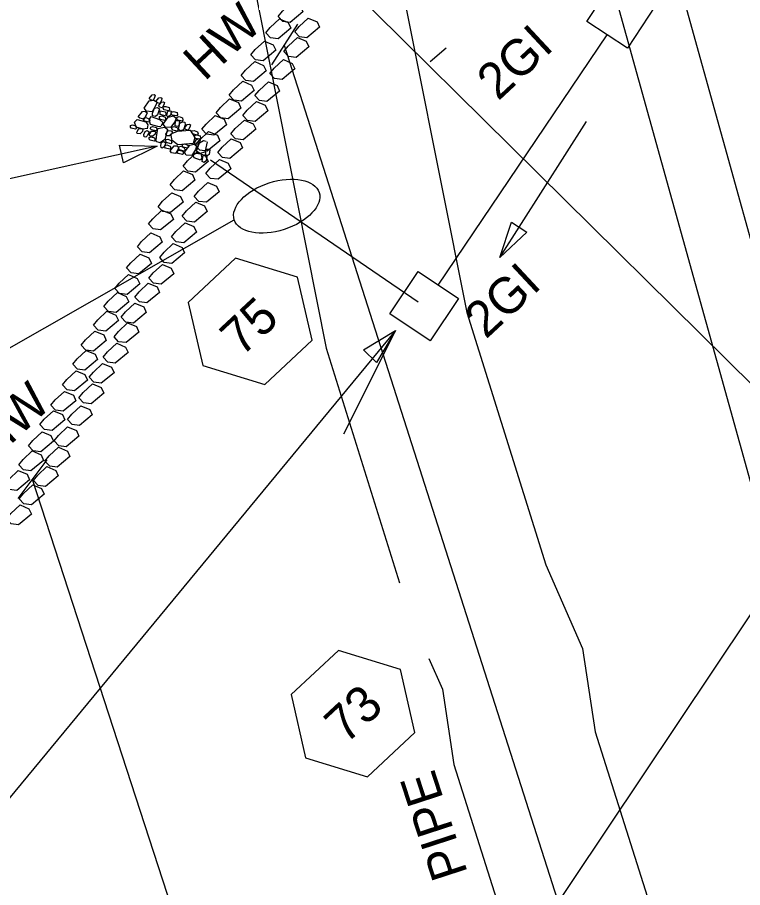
# Model space of a CAD drawing. Extents: x 2384780 to 2405432, y 547869 to 573706.
# Drawn here: x 2399532.6 to 2399632.8, y 561289.2 to 561409.4 of the extents above; entities that cross this region are included whole.
import ezdxf

# ---------------------------------------------------------------- set-up
doc = ezdxf.new("R2010")
doc.units = 0
for name, color, linetype in [('Old_Level_1', 7, 'Continuous'), ('Old_Level_10', 7, 'Continuous'), ('Old_Level_19', 7, 'Continuous'), ('Old_Level_20', 7, 'Continuous'), ('Old_Level_5', 7, 'Continuous'), ('Old_Level_63', 7, 'Continuous'), ('Old_Level_9', 7, 'Continuous'), ('Prop Buffer Zone 1', 7, 'Continuous'), ('Prop Buffer Zone 2', 7, 'Continuous'), ('Prop Drainage Box Number Symbol CELL', 7, 'Continuous')]:
    doc.layers.add(name, color=color, linetype=linetype)

# ---------------------------------------------------------------- blocks, each defined once
blk = doc.blocks.new('BUBBLE')
at = {"layer": 'Old_Level_10'}
blk.add_ellipse((0, 0), major_axis=(192.5, 153.8), ratio=0.548538, dxfattribs=at)

msp = doc.modelspace()

# ---------------------------------------------------------------- linework, layer by layer
at = {"layer": 'Old_Level_1'}
for p, q in [((2399590.77, 561372.41), (2399614.13, 561406.99)), ((2399641.65, 561180.06), (2399569.52, 561405.53)), ((2399551.91, 561391.59), (2399515.09, 561383.45)), ((2399588.02, 561370.04), (2399559.31, 561389.68)), ((2399605.31, 561128.58), (2399534.7, 561345.56))]:
    msp.add_line(p, q, dxfattribs=at)
for points in [[(2399551.93, 561397.67), (2399551.72, 561397.19), (2399551.23, 561396.35), (2399550.45, 561396.43), (2399550.15, 561396.87), (2399550.85, 561397.85), (2399551.48, 561397.95), (2399551.93, 561397.67)], [(2399551.67, 561398.63), (2399551.58, 561398.33), (2399551.36, 561397.89), (2399551.01, 561397.98), (2399550.83, 561398.18), (2399551.23, 561398.68), (2399551.53, 561398.75), (2399551.67, 561398.63)], [(2399552.6, 561398.22), (2399552.51, 561397.92), (2399552.28, 561397.48), (2399551.94, 561397.57), (2399551.75, 561397.77), (2399552.15, 561398.27), (2399552.45, 561398.34), (2399552.6, 561398.22)], [(2399552.94, 561397.62), (2399552.86, 561397.32), (2399552.64, 561396.88), (2399552.29, 561396.97), (2399552.11, 561397.17), (2399552.51, 561397.67), (2399552.81, 561397.74), (2399552.94, 561397.62)], [(2399550.55, 561396.22), (2399550.42, 561395.88), (2399550.08, 561395.34), (2399549.53, 561395.45), (2399549.33, 561395.66), (2399549.91, 561396.4), (2399550.29, 561396.44), (2399550.55, 561396.22)], [(2399551.28, 561395.78), (2399551.31, 561396.17), (2399551.58, 561396.84), (2399551.99, 561396.93), (2399552.25, 561396.76), (2399552, 561395.95), (2399551.71, 561395.69), (2399551.28, 561395.78)], [(2399552.37, 561396.47), (2399552.57, 561396.43), (2399553.09, 561396.35), (2399553.13, 561395.96), (2399553.03, 561395.81), (2399552.36, 561395.96), (2399552.34, 561396.22), (2399552.37, 561396.47)], [(2399552.78, 561397.06), (2399553.11, 561397.08), (2399553.6, 561396.94), (2399553.63, 561396.65), (2399553.54, 561396.5), (2399552.9, 561396.62), (2399552.77, 561396.84), (2399552.78, 561397.06)], [(2399553.2, 561395.73), (2399553.25, 561395.95), (2399553.42, 561396.42), (2399553.72, 561396.49), (2399553.86, 561396.42), (2399553.79, 561395.88), (2399553.53, 561395.69), (2399553.31, 561395.7)], [(2399553.93, 561396.31), (2399554.2, 561396.4), (2399554.68, 561396.24), (2399554.74, 561395.93), (2399554.64, 561395.77), (2399554.02, 561395.89), (2399553.89, 561396.11), (2399553.93, 561396.31)], [(2399550.51, 561394.02), (2399550, 561393.97), (2399549.01, 561394.23), (2399548.81, 561394.92), (2399549.19, 561395.3), (2399550.37, 561394.94), (2399550.65, 561394.54), (2399550.57, 561393.98)], [(2399550.09, 561395.47), (2399550.37, 561395.55), (2399550.85, 561395.4), (2399550.92, 561395.09), (2399550.82, 561394.93), (2399550.19, 561395.06), (2399550.05, 561395.27), (2399550.09, 561395.47)], [(2399552.45, 561394.26), (2399552.01, 561394.32), (2399550.99, 561394.6), (2399550.84, 561395.26), (2399551.11, 561395.71), (2399552.27, 561395.3), (2399552.7, 561394.85), (2399552.48, 561394.37)], [(2399552.26, 561395.71), (2399552.57, 561395.79), (2399553.04, 561395.62), (2399553.11, 561395.31), (2399552.98, 561395.17), (2399552.4, 561395.3), (2399552.25, 561395.49), (2399552.26, 561395.71)], [(2399554.58, 561395.47), (2399554.39, 561394.97), (2399553.77, 561394.16), (2399553.1, 561394.22), (2399552.75, 561394.65), (2399553.47, 561395.61), (2399554.17, 561395.8), (2399554.58, 561395.47)], [(2399554.41, 561394.4), (2399554.43, 561394.64), (2399554.52, 561395.17), (2399554.9, 561395.16), (2399555.04, 561395.07), (2399554.91, 561394.43), (2399554.72, 561394.33), (2399554.41, 561394.4)], [(2399554.69, 561395.59), (2399554.96, 561395.68), (2399555.44, 561395.52), (2399555.5, 561395.21), (2399555.4, 561395.05), (2399554.78, 561395.18), (2399554.65, 561395.39), (2399554.69, 561395.59)], [(2399548.23, 561394.47), (2399548.51, 561394.57), (2399548.98, 561394.4), (2399549.06, 561394.09), (2399548.93, 561393.95), (2399548.35, 561394.08), (2399548.24, 561394.24), (2399548.23, 561394.47)], [(2399549.96, 561393.93), (2399549.89, 561393.62), (2399549.58, 561393.32), (2399549.19, 561393.35), (2399549.1, 561393.55), (2399549.41, 561394.06), (2399549.8, 561394.03), (2399549.96, 561393.93)], [(2399551.05, 561394.24), (2399551.29, 561394.31), (2399551.84, 561394.16), (2399551.9, 561393.85), (2399551.77, 561393.72), (2399551.15, 561393.84), (2399551.03, 561393.99), (2399551.05, 561394.24)], [(2399551.8, 561392.34), (2399551.82, 561392.88), (2399552.02, 561394.05), (2399552.96, 561394.21), (2399553.37, 561393.96), (2399552.98, 561392.53), (2399552.36, 561392.08), (2399551.74, 561392.23)], [(2399554, 561394.23), (2399554.26, 561394.33), (2399554.73, 561394.13), (2399554.82, 561393.87), (2399554.7, 561393.68), (2399554.09, 561393.82), (2399553.96, 561394.04), (2399554, 561394.23)], [(2399555.75, 561394.9), (2399555.78, 561394.54), (2399555.59, 561393.86), (2399555.15, 561393.74), (2399554.9, 561393.9), (2399555.07, 561394.76), (2399555.44, 561394.98), (2399555.75, 561394.9)], [(2399556.54, 561394.54), (2399556.45, 561394.24), (2399556.23, 561393.8), (2399555.88, 561393.89), (2399555.69, 561394.09), (2399556.09, 561394.59), (2399556.4, 561394.66), (2399556.54, 561394.54)], [(2399550.14, 561392.87), (2399550.1, 561393.21), (2399550.26, 561393.62), (2399550.56, 561393.76), (2399550.82, 561393.6), (2399550.56, 561393.05), (2399550.35, 561392.84), (2399550.14, 561392.87)], [(2399550.83, 561392.79), (2399551.1, 561392.9), (2399551.57, 561392.73), (2399551.66, 561392.43), (2399551.53, 561392.29), (2399550.95, 561392.41), (2399550.83, 561392.57), (2399550.83, 561392.79)], [(2399551.7, 561393.57), (2399551.64, 561393.25), (2399551.34, 561392.96), (2399550.94, 561392.97), (2399550.85, 561393.17), (2399551.16, 561393.68), (2399551.55, 561393.67), (2399551.7, 561393.57)], [(2399554, 561393.64), (2399553.94, 561393.32), (2399553.63, 561393.03), (2399553.24, 561393.04), (2399553.15, 561393.24), (2399553.46, 561393.75), (2399553.84, 561393.74), (2399554, 561393.64)], [(2399553.97, 561393.33), (2399554.75, 561393.67), (2399556.49, 561393.79), (2399557.14, 561392.78), (2399556.92, 561391.98), (2399554.77, 561391.77), (2399554.01, 561392.38), (2399553.8, 561393.31)], [(2399556.74, 561393.7), (2399557.04, 561393.75), (2399557.52, 561393.59), (2399557.6, 561393.31), (2399557.48, 561393.12), (2399556.85, 561393.29), (2399556.73, 561393.48), (2399556.74, 561393.7)], [(2399557.12, 561393.09), (2399557.39, 561393.18), (2399557.86, 561393.02), (2399557.93, 561392.71), (2399557.83, 561392.55), (2399557.21, 561392.68), (2399557.08, 561392.89), (2399557.12, 561393.09)], [(2399552.47, 561391.43), (2399552.42, 561391.69), (2399552.54, 561392.1), (2399552.86, 561392.25), (2399553.14, 561392.08), (2399552.88, 561391.53), (2399552.64, 561391.33), (2399552.47, 561391.43)], [(2399552.98, 561391.71), (2399553.26, 561391.79), (2399553.73, 561391.62), (2399553.81, 561391.33), (2399553.68, 561391.19), (2399553.1, 561391.31), (2399552.99, 561391.48), (2399552.98, 561391.71)], [(2399553.15, 561392.51), (2399553.41, 561392.57), (2399553.86, 561392.39), (2399553.96, 561392.1), (2399553.83, 561391.91), (2399553.24, 561392.09), (2399553.14, 561392.29), (2399553.15, 561392.51)], [(2399554.9, 561391.51), (2399554.78, 561391.1), (2399554.47, 561390.59), (2399553.91, 561390.67), (2399553.73, 561390.97), (2399554.26, 561391.65), (2399554.65, 561391.66), (2399554.9, 561391.51)], [(2399554.93, 561391.51), (2399555.24, 561391.58), (2399555.68, 561391.38), (2399555.78, 561391.11), (2399555.66, 561390.92), (2399555.02, 561391.1), (2399554.92, 561391.29), (2399554.93, 561391.51)], [(2399555.43, 561391.83), (2399555.7, 561391.92), (2399556.17, 561391.75), (2399556.26, 561391.45), (2399556.13, 561391.31), (2399555.54, 561391.44), (2399555.42, 561391.61), (2399555.43, 561391.83)], [(2399557.41, 561391.64), (2399557.25, 561391.16), (2399556.72, 561390.3), (2399555.96, 561390.37), (2399555.72, 561390.75), (2399556.43, 561391.76), (2399557, 561391.88), (2399557.41, 561391.64)], [(2399557.88, 561392.41), (2399557.77, 561392.21), (2399557.54, 561391.83), (2399557.22, 561391.89), (2399557.06, 561391.99), (2399557.38, 561392.5), (2399557.72, 561392.64), (2399557.88, 561392.41)], [(2399558.83, 561392.21), (2399558.77, 561391.77), (2399558.51, 561390.78), (2399557.82, 561390.59), (2399557.39, 561390.91), (2399557.77, 561392.08), (2399558.33, 561392.4), (2399558.72, 561392.28)], [(2399554.73, 561390.96), (2399555.01, 561391.06), (2399555.48, 561390.89), (2399555.56, 561390.58), (2399555.43, 561390.44), (2399554.85, 561390.58), (2399554.72, 561390.74), (2399554.73, 561390.96)], [(2399556.98, 561390.64), (2399557.33, 561390.64), (2399557.95, 561390.52), (2399558.12, 561390), (2399557.92, 561389.66), (2399557.05, 561389.97), (2399556.9, 561390.29), (2399556.98, 561390.64)], [(2399558.58, 561390.43), (2399558.64, 561390.65), (2399558.7, 561391.19), (2399559.05, 561391.2), (2399559.21, 561391.1), (2399559.12, 561390.44), (2399558.83, 561390.27), (2399558.58, 561390.43)], [(2399558.16, 561389.5), (2399558.21, 561389.74), (2399558.29, 561390.31), (2399558.63, 561390.27), (2399558.79, 561390.18), (2399558.69, 561389.57), (2399558.41, 561389.35), (2399558.16, 561389.5)]]:
    msp.add_lwpolyline(points, dxfattribs=at)
for points in [[(2399546.75, 561391.73), (2399551.91, 561391.59), (2399547.29, 561389.29)], [(2399584.09, 561368.41), (2399587.98, 561374.26), (2399593.57, 561370.55), (2399589.68, 561364.71)]]:
    msp.add_lwpolyline(points, close=True, dxfattribs=at)
at = {"layer": 'Old_Level_10'}
for p, q in [((2399672.4, 561240.4), (2399616.91, 561439.98)), ((2399665.8, 561230.54), (2399610.31, 561430.11))]:
    msp.add_line(p, q, dxfattribs=at)
at = {"layer": 'Old_Level_19'}
msp.add_lwpolyline([(2399935.16, 561841.93), (2399903.83, 561780.72), (2399876, 561728.1), (2399849.43, 561679.29), (2399802.46, 561596.2), (2399773.68, 561547.14), (2399723.96, 561465.41), (2399672.86, 561385.1), (2399604.3, 561282.61), (2399518.27, 561161.65)], dxfattribs=at)
at = {"layer": 'Old_Level_20'}
for points in [[(2399568.64, 561409.53), (2399569.24, 561410.27), (2399570.51, 561411.45), (2399571.73, 561410.94), (2399572.08, 561410.17), (2399570.33, 561408.71), (2399569.28, 561408.84), (2399568.64, 561409.53)], [(2399566.96, 561407.27), (2399567.56, 561408), (2399568.83, 561409.19), (2399570.05, 561408.67), (2399570.4, 561407.9), (2399568.65, 561406.44), (2399567.6, 561406.58), (2399566.96, 561407.27)], [(2399570.94, 561407.39), (2399571.54, 561408.13), (2399572.81, 561409.31), (2399574.03, 561408.8), (2399574.38, 561408.03), (2399572.62, 561406.57), (2399571.58, 561406.7), (2399570.94, 561407.39)], [(2399564.88, 561404.21), (2399565.48, 561404.95), (2399566.75, 561406.13), (2399567.97, 561405.62), (2399568.32, 561404.85), (2399566.56, 561403.39), (2399565.52, 561403.52), (2399564.88, 561404.21)], [(2399569.44, 561404.68), (2399570.04, 561405.42), (2399571.31, 561406.61), (2399572.53, 561406.09), (2399572.88, 561405.32), (2399571.13, 561403.86), (2399570.08, 561403.99), (2399569.44, 561404.68)], [(2399563.54, 561401.36), (2399564.14, 561402.09), (2399565.42, 561403.28), (2399566.64, 561402.76), (2399566.98, 561402), (2399565.23, 561400.54), (2399564.19, 561400.67), (2399563.54, 561401.36)], [(2399567.51, 561401.64), (2399568.11, 561402.37), (2399569.38, 561403.56), (2399570.6, 561403.04), (2399570.95, 561402.27), (2399569.19, 561400.81), (2399568.15, 561400.95), (2399567.51, 561401.64)], [(2399561.9, 561398.64), (2399562.49, 561399.37), (2399563.77, 561400.56), (2399564.99, 561400.04), (2399565.34, 561399.27), (2399563.58, 561397.82), (2399562.54, 561397.95), (2399561.9, 561398.64)], [(2399565.42, 561398.58), (2399566.02, 561399.31), (2399567.3, 561400.5), (2399568.52, 561399.98), (2399568.86, 561399.22), (2399567.11, 561397.76), (2399566.07, 561397.89), (2399565.42, 561398.58)], [(2399560.07, 561396.21), (2399560.67, 561396.95), (2399561.94, 561398.13), (2399563.16, 561397.62), (2399563.51, 561396.85), (2399561.76, 561395.39), (2399560.71, 561395.52), (2399560.07, 561396.21)], [(2399563.78, 561395.86), (2399564.37, 561396.59), (2399565.65, 561397.78), (2399566.87, 561397.26), (2399567.22, 561396.49), (2399565.46, 561395.03), (2399564.42, 561395.17), (2399563.78, 561395.86)], [(2399558.09, 561393.93), (2399558.69, 561394.66), (2399559.96, 561395.85), (2399561.18, 561395.33), (2399561.53, 561394.56), (2399559.77, 561393.1), (2399558.73, 561393.24), (2399558.09, 561393.93)], [(2399562.12, 561393.29), (2399562.72, 561394.03), (2399563.99, 561395.21), (2399565.21, 561394.7), (2399565.56, 561393.93), (2399563.8, 561392.47), (2399562.76, 561392.6), (2399562.12, 561393.29)], [(2399557.17, 561391.72), (2399557.77, 561392.45), (2399559.04, 561393.64), (2399560.26, 561393.12), (2399560.61, 561392.35), (2399558.85, 561390.9), (2399557.81, 561391.03), (2399557.17, 561391.72)], [(2399560.3, 561390.71), (2399560.9, 561391.45), (2399562.18, 561392.63), (2399563.4, 561392.12), (2399563.74, 561391.35), (2399561.99, 561389.89), (2399560.95, 561390.02), (2399560.3, 561390.71)], [(2399555.53, 561388.84), (2399556.13, 561389.58), (2399557.4, 561390.77), (2399558.62, 561390.25), (2399558.97, 561389.48), (2399557.22, 561388.02), (2399556.17, 561388.16), (2399555.53, 561388.84)], [(2399558.67, 561387.84), (2399559.27, 561388.57), (2399560.54, 561389.76), (2399561.76, 561389.24), (2399562.11, 561388.48), (2399560.35, 561387.02), (2399559.31, 561387.15), (2399558.67, 561387.84)], [(2399553.72, 561386.27), (2399554.32, 561387), (2399555.59, 561388.19), (2399556.81, 561387.67), (2399557.16, 561386.9), (2399555.4, 561385.44), (2399554.36, 561385.58), (2399553.72, 561386.27)], [(2399557.05, 561384.66), (2399557.65, 561385.4), (2399558.92, 561386.58), (2399560.14, 561386.07), (2399560.49, 561385.3), (2399558.73, 561383.84), (2399557.69, 561383.97), (2399557.05, 561384.66)], [(2399552.09, 561383.24), (2399552.69, 561383.98), (2399553.96, 561385.16), (2399555.18, 561384.65), (2399555.53, 561383.88), (2399553.78, 561382.42), (2399552.73, 561382.55), (2399552.09, 561383.24)], [(2399555.4, 561381.94), (2399556, 561382.68), (2399557.27, 561383.86), (2399558.49, 561383.35), (2399558.84, 561382.58), (2399557.08, 561381.12), (2399556.04, 561381.25), (2399555.4, 561381.94)], [(2399550.73, 561380.85), (2399551.33, 561381.58), (2399552.6, 561382.77), (2399553.82, 561382.25), (2399554.17, 561381.48), (2399552.41, 561380.02), (2399551.37, 561380.16), (2399550.73, 561380.85)], [(2399553.92, 561379.08), (2399554.51, 561379.81), (2399555.79, 561381), (2399557.01, 561380.48), (2399557.36, 561379.71), (2399555.6, 561378.25), (2399554.56, 561378.39), (2399553.92, 561379.08)], [(2399549.2, 561377.68), (2399549.79, 561378.42), (2399551.07, 561379.61), (2399552.29, 561379.09), (2399552.64, 561378.32), (2399550.88, 561376.86), (2399549.84, 561377), (2399549.2, 561377.68)], [(2399552.28, 561376.2), (2399552.88, 561376.94), (2399554.15, 561378.13), (2399555.37, 561377.61), (2399555.72, 561376.84), (2399553.96, 561375.38), (2399552.92, 561375.52), (2399552.28, 561376.2)], [(2399547.7, 561374.77), (2399548.29, 561375.5), (2399549.57, 561376.69), (2399550.79, 561376.17), (2399551.13, 561375.4), (2399549.38, 561373.94), (2399548.34, 561374.08), (2399547.7, 561374.77)], [(2399550.79, 561373.34), (2399551.39, 561374.08), (2399552.66, 561375.27), (2399553.88, 561374.75), (2399554.23, 561373.98), (2399552.48, 561372.52), (2399551.43, 561372.65), (2399550.79, 561373.34)], [(2399546.1, 561371.93), (2399546.7, 561372.66), (2399547.97, 561373.85), (2399549.19, 561373.33), (2399549.54, 561372.56), (2399547.79, 561371.1), (2399546.74, 561371.24), (2399546.1, 561371.93)], [(2399548.83, 561370.75), (2399549.43, 561371.49), (2399550.7, 561372.68), (2399551.92, 561372.16), (2399552.27, 561371.39), (2399550.51, 561369.93), (2399549.47, 561370.07), (2399548.83, 561370.75)], [(2399544.57, 561369.43), (2399545.17, 561370.17), (2399546.44, 561371.36), (2399547.66, 561370.84), (2399548.01, 561370.07), (2399546.26, 561368.61), (2399545.21, 561368.75), (2399544.57, 561369.43)], [(2399546.98, 561367.98), (2399547.57, 561368.72), (2399548.85, 561369.9), (2399550.07, 561369.39), (2399550.42, 561368.62), (2399548.66, 561367.16), (2399547.62, 561367.29), (2399546.98, 561367.98)], [(2399543.13, 561366.86), (2399543.73, 561367.6), (2399545, 561368.78), (2399546.22, 561368.27), (2399546.57, 561367.5), (2399544.82, 561366.04), (2399543.77, 561366.17), (2399543.13, 561366.86)], [(2399545.97, 561365.27), (2399546.57, 561366), (2399547.84, 561367.19), (2399549.06, 561366.67), (2399549.41, 561365.91), (2399547.66, 561364.45), (2399546.61, 561364.58), (2399545.97, 561365.27)], [(2399541.45, 561364.1), (2399542.05, 561364.84), (2399543.32, 561366.02), (2399544.54, 561365.51), (2399544.89, 561364.74), (2399543.13, 561363.28), (2399542.09, 561363.41), (2399541.45, 561364.1)], [(2399544.47, 561362.44), (2399545.06, 561363.17), (2399546.34, 561364.36), (2399547.56, 561363.84), (2399547.91, 561363.07), (2399546.15, 561361.61), (2399545.11, 561361.75), (2399544.47, 561362.44)], [(2399540.27, 561361.46), (2399540.87, 561362.2), (2399542.14, 561363.38), (2399543.36, 561362.87), (2399543.71, 561362.1), (2399541.96, 561360.64), (2399540.91, 561360.77), (2399540.27, 561361.46)], [(2399542.53, 561359.66), (2399543.13, 561360.39), (2399544.4, 561361.58), (2399545.62, 561361.06), (2399545.97, 561360.29), (2399544.21, 561358.83), (2399543.17, 561358.97), (2399542.53, 561359.66)], [(2399538.85, 561358.63), (2399539.45, 561359.37), (2399540.72, 561360.56), (2399541.94, 561360.04), (2399542.29, 561359.27), (2399540.53, 561357.81), (2399539.49, 561357.95), (2399538.85, 561358.63)], [(2399541.11, 561356.83), (2399541.71, 561357.57), (2399542.98, 561358.75), (2399544.2, 561358.24), (2399544.55, 561357.47), (2399542.79, 561356.01), (2399541.75, 561356.14), (2399541.11, 561356.83)], [(2399537.26, 561355.79), (2399537.86, 561356.53), (2399539.13, 561357.72), (2399540.35, 561357.2), (2399540.7, 561356.43), (2399538.94, 561354.97), (2399537.9, 561355.11), (2399537.26, 561355.79)], [(2399539.53, 561353.82), (2399540.13, 561354.56), (2399541.4, 561355.74), (2399542.62, 561355.23), (2399542.97, 561354.46), (2399541.21, 561353), (2399540.17, 561353.13), (2399539.53, 561353.82)], [(2399535.74, 561353.13), (2399536.34, 561353.87), (2399537.61, 561355.05), (2399538.83, 561354.54), (2399539.18, 561353.77), (2399537.42, 561352.31), (2399536.38, 561352.44), (2399535.74, 561353.13)], [(2399534.15, 561350.21), (2399534.75, 561350.94), (2399536.03, 561352.13), (2399537.25, 561351.61), (2399537.59, 561350.84), (2399535.84, 561349.38), (2399534.8, 561349.52), (2399534.15, 561350.21)], [(2399537.69, 561350.88), (2399538.29, 561351.62), (2399539.56, 561352.8), (2399540.78, 561352.29), (2399541.13, 561351.52), (2399539.37, 561350.06), (2399538.33, 561350.19), (2399537.69, 561350.88)], [(2399532.81, 561347.56), (2399533.4, 561348.29), (2399534.68, 561349.48), (2399535.9, 561348.96), (2399536.24, 561348.19), (2399534.49, 561346.73), (2399533.45, 561346.87), (2399532.81, 561347.56)], [(2399536.43, 561348.06), (2399537.03, 561348.8), (2399538.31, 561349.99), (2399539.53, 561349.47), (2399539.87, 561348.7), (2399538.12, 561347.24), (2399537.08, 561347.38), (2399536.43, 561348.06)], [(2399534.83, 561345.4), (2399535.43, 561346.13), (2399536.7, 561347.32), (2399537.92, 561346.8), (2399538.27, 561346.03), (2399536.51, 561344.57), (2399535.47, 561344.71), (2399534.83, 561345.4)], [(2399530.86, 561344.86), (2399531.46, 561345.6), (2399532.73, 561346.79), (2399533.95, 561346.27), (2399534.3, 561345.5), (2399532.55, 561344.04), (2399531.5, 561344.17), (2399530.86, 561344.86)], [(2399532.88, 561342.87), (2399533.48, 561343.61), (2399534.75, 561344.8), (2399535.97, 561344.28), (2399536.32, 561343.51), (2399534.56, 561342.05), (2399533.52, 561342.18), (2399532.88, 561342.87)], [(2399531.11, 561340.11), (2399531.71, 561340.84), (2399532.98, 561342.03), (2399534.2, 561341.51), (2399534.55, 561340.74), (2399532.79, 561339.28), (2399531.75, 561339.42), (2399531.11, 561340.11)]]:
    msp.add_lwpolyline(points, dxfattribs=at)
at = {"layer": 'Old_Level_5'}
for p, q in [((2399571.31, 561408.48), (2399567.72, 561402.82)), ((2399589.68, 561403.3), (2399591.85, 561405.19)), ((2399599.28, 561376.2), (2399611.26, 561395.02)), ((2399524.65, 561359.82), (2399562.59, 561381.43)), ((2399584.85, 561366.13), (2399515.08, 561281.64)), ((2399536.7, 561348.28), (2399532.7, 561342.91))]:
    msp.add_line(p, q, dxfattribs=at)
for points in [[(2399603.02, 561379.74), (2399599.28, 561376.2), (2399600.91, 561381.08)], [(2399580.46, 561363.44), (2399584.85, 561366.13), (2399582.24, 561361.69)]]:
    msp.add_lwpolyline(points, close=True, dxfattribs=at)
at = {"layer": 'Old_Level_63'}
msp.add_lwpolyline([(2399645.61, 561347.28), (2398726.19, 562255.29), (2398336.6, 562216.19)], dxfattribs=at)
msp.add_circle((2399645.61, 561347.28), 187.94, dxfattribs=at)
at = {"layer": 'Old_Level_9'}
msp.add_line((2399584.85, 561366.13), (2399577.7, 561351.82), dxfattribs=at)
msp.add_lwpolyline([(2399611.32, 561408.81), (2399615.16, 561414.7), (2399620.78, 561411.03), (2399616.94, 561405.16)], close=True, dxfattribs=at)
at = {"layer": 'Prop Buffer Zone 1'}
msp.add_lwpolyline([(2399551.38, 561612.17), (2399546.02, 561604.52), (2399534.7, 561584.54), (2399541.09, 561550.93), (2399547.21, 561545.6), (2399547.98, 561538.32), (2399571.27, 561475.96), (2399577.41, 561467.66), (2399570.54, 561457.45), (2399583.91, 561422.91), (2399594.71, 561368.62), (2399605.62, 561333.74), (2399610.73, 561322.17), (2399612.45, 561310.67), (2399625.7, 561268.9), (2399637.19, 561243.08), (2399649.65, 561200.79), (2399658.42, 561177.62)], dxfattribs=at)
at = {"layer": 'Prop Buffer Zone 2'}
for points in [[(2399545.02, 561489.08), (2399553.12, 561467.4), (2399548.12, 561459.96), (2399564.63, 561417.31), (2399575.3, 561363.67), (2399585.44, 561331.26)], [(2399589.47, 561320.79), (2399591.35, 561316.55), (2399592.91, 561306.14), (2399606.97, 561261.79), (2399618.38, 561236.16), (2399630.68, 561194.41), (2399641.75, 561165.18)]]:
    msp.add_lwpolyline(points, dxfattribs=at)
at = {"layer": 'Prop Drainage Box Number Symbol CELL'}
for points in [[(2399571.32, 561373.51), (2399562.76, 561376.12), (2399556.22, 561370.02), (2399558.23, 561361.3), (2399566.79, 561358.68), (2399573.33, 561364.79)], [(2399585.54, 561319.31), (2399576.98, 561321.92), (2399570.44, 561315.82), (2399572.45, 561307.1), (2399581.01, 561304.48), (2399587.55, 561310.59)]]:
    msp.add_lwpolyline(points, close=True, dxfattribs=at)

# ---------------------------------------------------------------- block references
at = {"layer": 'Old_Level_5', "xscale": 0.025000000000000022, "yscale": 0.025000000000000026, "rotation": 159.197785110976}
msp.add_blockref('BUBBLE', (2399568.45, 561383.31), dxfattribs=at)

# ---------------------------------------------------------------- texts
at = {"layer": 'Old_Level_1'}
msp.add_text('2GI', height=5, rotation=43, dxfattribs=at).set_placement((2399597.36, 561364.85))
at = {"layer": 'Old_Level_5'}
for s, rotation, p in [('HW', 43, (2399558.49, 561400.47)), ('2GI', 43, (2399599.05, 561397.76)), ('HW', 43, (2399529.33, 561348.1)), ('FLOODPLAIN OVERFLOW PIPE', 108.0266, (2399620.98, 561210.98))]:
    msp.add_text(s, height=5, rotation=rotation, dxfattribs=at).set_placement(p)
at = {"layer": 'Prop Drainage Box Number Symbol CELL'}
for s, p in [('75', (2399563.59, 561362.4)), ('73', (2399578, 561308.86))]:
    msp.add_text(s, height=5, rotation=43, dxfattribs=at).set_placement(p)

doc.saveas('drawing.dxf')
